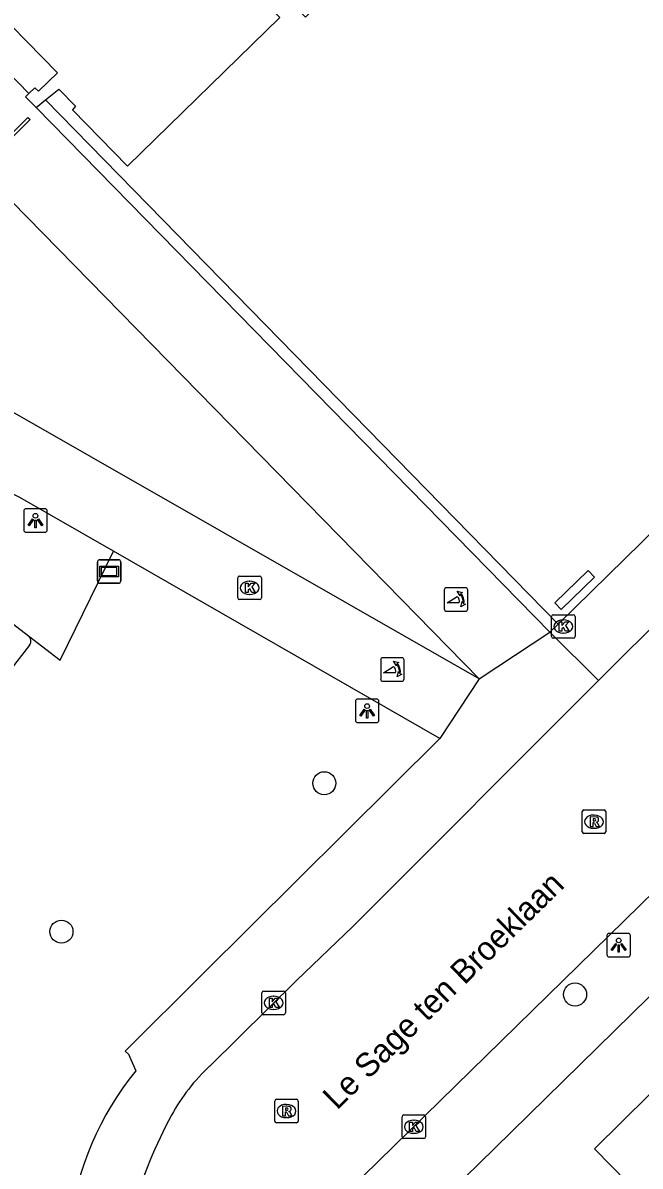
# Model space of a CAD drawing. Extents: x 161402 to 161933, y 381650 to 382313.
# Drawn here: x 161761.63 to 161787.85, y 382103.64 to 382152.18 of the extents above; entities that cross this region are included whole.
import ezdxf

# ---------------------------------------------------------------- set-up
doc = ezdxf.new("R2010")
doc.units = 0
for name, color, linetype in [('IMGEO_Boom', 7, 'Continuous'), ('IMGEO_Groenvoorziening', 7, 'Continuous'), ('IMGEO_Haag', 7, 'Continuous'), ('IMGEO_Kolk', 7, 'Continuous'), ('IMGEO_Lichtpunt', 7, 'Continuous'), ('IMGEO_Lijnafwatering', 7, 'Continuous'), ('IMGEO_Muur', 7, 'Continuous'), ('IMGEO_Openbare_ruimte_label', 7, 'Continuous'), ('IMGEO_Pand', 7, 'Continuous'), ('IMGEO_Pand_overbouw', 7, 'Continuous'), ('IMGEO_Parkeervlak_open', 7, 'Continuous'), ('IMGEO_Poller', 7, 'Continuous'), ('IMGEO_Reclamebord', 7, 'Continuous'), ('IMGEO_Rijbaan_lokaal_gesloten', 7, 'Continuous'), ('IMGEO_Rioolput', 7, 'Continuous'), ('IMGEO_Voetpad_open', 7, 'Continuous')]:
    doc.layers.add(name, color=color, linetype=linetype)

msp = doc.modelspace()

# ---------------------------------------------------------------- linework, layer by layer
at = {"layer": 'IMGEO_Boom'}
for centre in [(161774.437, 382119.897), (161763.272, 382113.595), (161785.089, 382110.925)]:
    msp.add_circle(centre, 0.489, dxfattribs=at)
at = {"layer": 'IMGEO_Groenvoorziening'}
msp.add_lwpolyline([(161761.867, 382126.157), (161763.216, 382125.122), (161765.481, 382129.756)], dxfattribs=at)
at = {"layer": 'IMGEO_Haag'}
msp.add_lwpolyline([(161784.501, 382127.274), (161784.224, 382127.562), (161785.644, 382128.928), (161785.921, 382128.64), (161784.501, 382127.274)], dxfattribs=at)
at = {"layer": 'IMGEO_Kolk'}
for p, q in [((161770.762, 382127.768), (161770.762, 382128.62)), ((161770.837, 382128.694), (161771.689, 382128.694)), ((161771.25, 382128.474), (161771.275, 382128.474)), ((161771.763, 382128.62), (161771.763, 382127.768)), ((161771.273, 382127.914), (161771.248, 382127.914)), ((161771.689, 382127.694), (161770.837, 382127.694)), ((161784.088, 382126.124), (161784.088, 382126.976)), ((161784.163, 382127.05), (161785.015, 382127.05)), ((161785.089, 382126.976), (161785.089, 382126.124)), ((161784.576, 382126.83), (161784.601, 382126.83)), ((161785.015, 382126.05), (161784.163, 382126.05)), ((161784.599, 382126.27), (161784.574, 382126.27)), ((161771.782, 382110.142), (161771.782, 382110.994)), ((161771.857, 382111.068), (161772.709, 382111.068)), ((161772.27, 382110.848), (161772.295, 382110.848)), ((161772.783, 382110.994), (161772.783, 382110.142)), ((161772.709, 382110.068), (161771.857, 382110.068)), ((161772.293, 382110.288), (161772.268, 382110.288)), ((161777.739, 382104.884), (161777.739, 382105.736)), ((161777.814, 382105.81), (161778.666, 382105.81)), ((161778.227, 382105.59), (161778.252, 382105.59)), ((161778.74, 382105.736), (161778.74, 382104.884)), ((161778.25, 382105.03), (161778.225, 382105.03)), ((161778.666, 382104.81), (161777.814, 382104.81))]:
    msp.add_line(p, q, dxfattribs=at)
for points in [[(161770.762, 382127.768), (161770.762, 382128.62)], [(161770.837, 382128.694), (161771.689, 382128.694)], [(161771.083, 382128.394), (161771.206, 382128.394), (161771.206, 382128.243), (161771.336, 382128.394), (161771.5, 382128.394), (161771.354, 382128.243), (161771.507, 382127.994), (161771.355, 382127.994), (161771.27, 382128.158), (161771.206, 382128.091), (161771.206, 382127.994), (161771.083, 382127.994), (161771.083, 382128.394)], [(161771.763, 382128.62), (161771.763, 382127.768)], [(161771.689, 382127.694), (161770.837, 382127.694)], [(161784.088, 382126.124), (161784.088, 382126.976)], [(161784.163, 382127.05), (161785.015, 382127.05)], [(161785.089, 382126.976), (161785.089, 382126.124)], [(161784.409, 382126.75), (161784.532, 382126.75), (161784.532, 382126.599), (161784.662, 382126.75), (161784.826, 382126.75), (161784.68, 382126.599), (161784.833, 382126.35), (161784.681, 382126.35), (161784.596, 382126.514), (161784.532, 382126.447), (161784.532, 382126.35), (161784.409, 382126.35), (161784.409, 382126.75)], [(161785.015, 382126.05), (161784.163, 382126.05)], [(161771.782, 382110.142), (161771.782, 382110.994)], [(161771.857, 382111.068), (161772.709, 382111.068)], [(161772.783, 382110.994), (161772.783, 382110.142)], [(161772.103, 382110.768), (161772.226, 382110.768), (161772.226, 382110.617), (161772.356, 382110.768), (161772.52, 382110.768), (161772.374, 382110.617), (161772.527, 382110.368), (161772.375, 382110.368), (161772.29, 382110.532), (161772.226, 382110.465), (161772.226, 382110.368), (161772.103, 382110.368), (161772.103, 382110.768)], [(161772.709, 382110.068), (161771.857, 382110.068)], [(161777.739, 382104.884), (161777.739, 382105.736)], [(161777.814, 382105.81), (161778.666, 382105.81)], [(161778.06, 382105.51), (161778.183, 382105.51), (161778.183, 382105.359), (161778.313, 382105.51), (161778.477, 382105.51), (161778.331, 382105.359), (161778.484, 382105.11), (161778.332, 382105.11), (161778.247, 382105.274), (161778.183, 382105.207), (161778.183, 382105.11), (161778.06, 382105.11), (161778.06, 382105.51)], [(161778.74, 382105.736), (161778.74, 382104.884)], [(161778.666, 382104.81), (161777.814, 382104.81)]]:
    msp.add_lwpolyline(points, dxfattribs=at)
for centre, start, end in [((161770.839, 382128.618), 91.552, 178.448), ((161770.839, 382128.618), 91.552, 178.448), ((161771.687, 382128.618), 1.552, 88.448), ((161771.687, 382128.618), 1.552, 88.448), ((161770.839, 382127.77), 181.552, 268.448), ((161770.839, 382127.77), 181.552, 268.448), ((161771.687, 382127.77), 271.552, 358.448), ((161771.687, 382127.77), 271.552, 358.448), ((161784.165, 382126.974), 91.552, 178.448), ((161784.165, 382126.974), 91.552, 178.448), ((161785.013, 382126.974), 1.552, 88.448), ((161785.013, 382126.974), 1.552, 88.448), ((161784.165, 382126.126), 181.552, 268.448), ((161784.165, 382126.126), 181.552, 268.448), ((161785.013, 382126.126), 271.552, 358.448), ((161785.013, 382126.126), 271.552, 358.448), ((161771.859, 382110.992), 91.552, 178.448), ((161771.859, 382110.992), 91.552, 178.448), ((161772.707, 382110.992), 1.552, 88.448), ((161772.707, 382110.992), 1.552, 88.448), ((161771.859, 382110.144), 181.552, 268.448), ((161771.859, 382110.144), 181.552, 268.448), ((161772.707, 382110.144), 271.552, 358.448), ((161772.707, 382110.144), 271.552, 358.448), ((161777.816, 382105.734), 91.552, 178.448), ((161777.816, 382105.734), 91.552, 178.448), ((161778.664, 382105.734), 1.552, 88.448), ((161778.664, 382105.734), 1.552, 88.448), ((161777.816, 382104.886), 181.552, 268.448), ((161777.816, 382104.886), 181.552, 268.448), ((161778.664, 382104.886), 271.552, 358.448), ((161778.664, 382104.886), 271.552, 358.448)]:
    msp.add_arc(centre, 0.0765, start, end, dxfattribs=at)
for centre, major_axis, ratio, start_param, end_param in [((161771.249, 382128.194), (-0.387, 0.002), 0.722429, 4.712389, 7.853982), ((161771.274, 382128.194), (-0.39, 0.002), 0.717154, 1.570796, 4.712389), ((161784.575, 382126.55), (-0.387, 0.002), 0.722429, 4.712389, 7.853982), ((161784.6, 382126.55), (-0.39, 0.002), 0.717154, 1.570796, 4.712389), ((161772.269, 382110.568), (-0.387, 0.002), 0.722429, 4.712389, 7.853982), ((161772.294, 382110.568), (-0.39, 0.002), 0.717154, 1.570796, 4.712389), ((161778.226, 382105.31), (-0.387, 0.002), 0.722429, 4.712389, 7.853982), ((161778.251, 382105.31), (-0.39, 0.002), 0.717154, 1.570796, 4.712389)]:
    msp.add_ellipse(centre, major_axis=major_axis, ratio=ratio, start_param=start_param, end_param=end_param, dxfattribs=at)
at = {"layer": 'IMGEO_Lichtpunt'}
for p, q in [((161761.669, 382131.454), (161761.669, 382130.647)), ((161761.669, 382131.454), (161761.669, 382130.647)), ((161762.571, 382131.549), (161761.763, 382131.549)), ((161762.571, 382131.549), (161761.763, 382131.549)), ((161762.665, 382130.647), (161762.665, 382131.454)), ((161762.665, 382130.647), (161762.665, 382131.454)), ((161761.763, 382130.553), (161762.571, 382130.553)), ((161761.763, 382130.553), (161762.571, 382130.553)), ((161776.659, 382123.467), (161775.851, 382123.467)), ((161776.659, 382123.467), (161775.851, 382123.467)), ((161775.757, 382123.372), (161775.757, 382122.565)), ((161775.757, 382123.372), (161775.757, 382122.565)), ((161776.753, 382122.565), (161776.753, 382123.372)), ((161776.753, 382122.565), (161776.753, 382123.372)), ((161775.851, 382122.471), (161776.659, 382122.471)), ((161775.851, 382122.471), (161776.659, 382122.471)), ((161786.442, 382113.424), (161786.442, 382112.617)), ((161786.442, 382113.424), (161786.442, 382112.617)), ((161787.344, 382113.519), (161786.536, 382113.519)), ((161787.344, 382113.519), (161786.536, 382113.519)), ((161787.438, 382112.617), (161787.438, 382113.424)), ((161787.438, 382112.617), (161787.438, 382113.424)), ((161786.536, 382112.523), (161787.344, 382112.523)), ((161786.536, 382112.523), (161787.344, 382112.523))]:
    msp.add_line(p, q, dxfattribs=at)
for points in [[(161762.043, 382131.118), (161762.082, 382131.09), (161761.894, 382130.828), (161761.856, 382130.855), (161762.043, 382131.118)], [(161762.145, 382131.07), (161762.192, 382131.07), (161762.192, 382130.748), (161762.145, 382130.748), (161762.145, 382131.07)], [(161762.255, 382131.09), (161762.293, 382131.117), (161762.48, 382130.855), (161762.441, 382130.827), (161762.255, 382131.09)], [(161776.131, 382123.036), (161776.17, 382123.008), (161775.982, 382122.746), (161775.944, 382122.773), (161776.131, 382123.036)], [(161776.233, 382122.988), (161776.28, 382122.988), (161776.28, 382122.666), (161776.233, 382122.666), (161776.233, 382122.988)], [(161776.343, 382123.008), (161776.381, 382123.035), (161776.568, 382122.773), (161776.529, 382122.745), (161776.343, 382123.008)], [(161786.816, 382113.088), (161786.855, 382113.06), (161786.667, 382112.798), (161786.629, 382112.825), (161786.816, 382113.088)], [(161786.918, 382113.04), (161786.965, 382113.04), (161786.965, 382112.718), (161786.918, 382112.718), (161786.918, 382113.04)], [(161787.028, 382113.06), (161787.066, 382113.087), (161787.253, 382112.825), (161787.214, 382112.797), (161787.028, 382113.06)]]:
    msp.add_lwpolyline(points, dxfattribs=at)
for centre in [(161762.168, 382131.252), (161776.256, 382123.17), (161786.941, 382113.222)]:
    msp.add_circle(centre, 0.0994, dxfattribs=at)
for centre, start, end in [((161761.763, 382131.454), 90, 180), ((161761.763, 382131.454), 90, 180), ((161762.571, 382131.454), 0, 90), ((161762.571, 382131.454), 0, 90), ((161761.763, 382130.647), 180, 270), ((161761.763, 382130.647), 180, 270), ((161762.571, 382130.647), 270, 0), ((161762.571, 382130.647), 270, 360), ((161775.851, 382123.372), 90, 180), ((161775.851, 382123.372), 90, 180), ((161776.659, 382123.372), 0, 90), ((161776.659, 382123.372), 0, 90), ((161775.851, 382122.565), 180, 270), ((161775.851, 382122.565), 180, 270), ((161776.659, 382122.565), 270, 0), ((161776.659, 382122.565), 270, 360), ((161786.536, 382113.424), 90, 180), ((161786.536, 382113.424), 90, 180), ((161787.344, 382113.424), 0, 90), ((161787.344, 382113.424), 0, 90), ((161786.536, 382112.617), 180, 270), ((161786.536, 382112.617), 180, 270), ((161787.344, 382112.617), 270, 0), ((161787.344, 382112.617), 270, 360)]:
    msp.add_arc(centre, 0.0946, start, end, dxfattribs=at)
at = {"layer": 'IMGEO_Lijnafwatering'}
msp.add_lwpolyline([(161759.72, 382146.044), (161761.845, 382148.166), (161761.94, 382148.087), (161759.814, 382145.96)], dxfattribs=at)
at = {"layer": 'IMGEO_Muur'}
for points in [[(161762.597, 382148.916), (161784.374, 382126.65)], [(161784.015, 382126.305), (161762.198, 382148.594)], [(161784.374, 382126.65), (161784.015, 382126.305)], [(161769.279, 382111.799), (161765.984, 382108.524), (161766.123, 382108.385), (161766.425, 382107.684)]]:
    msp.add_lwpolyline(points, dxfattribs=at)
msp.add_arc((161776.479, 382099.495), 12.967, 140.8362, 172.8403, dxfattribs=at)
at = {"layer": 'IMGEO_Pand'}
for points in [[(161762.198, 382148.594), (161761.744, 382149.047), (161761.891, 382149.186), (161762.139, 382149.42), (161762.295, 382149.283), (161763.101, 382150.057), (161760.483, 382152.716), (161759.531, 382151.588), (161721.45, 382190.492)], [(161762.597, 382148.916), (161763.156, 382149.374), (161763.873, 382148.642), (161763.738, 382148.49), (161766.077, 382146.095), (161772.542, 382152.417), (161769.948, 382155.069), (161770.562, 382155.574), (161773.637, 382152.427), (161780.106, 382158.747), (161777.513, 382161.4), (161785.428, 382168.061), (161805.657, 382147.504)], [(161762.198, 382148.594), (161762.597, 382148.916)], [(161812.975, 382087.217), (161811.601, 382088.614), (161806.434, 382083.531), (161789.417, 382100.81), (161785.909, 382104.373), (161789.402, 382107.818), (161793.08, 382111.447), (161793.922, 382110.604), (161796.076, 382112.783), (161795.307, 382113.643), (161799.066, 382117.315), (161802.484, 382120.653), (161805.97, 382117.113), (161810.796, 382121.845), (161807.594, 382125.104), (161806.847, 382124.385), (161806.553, 382124.686), (161817.329, 382135.274)]]:
    msp.add_lwpolyline(points, dxfattribs=at)
at = {"layer": 'IMGEO_Pand_overbouw'}
msp.add_lwpolyline([(161761.891, 382149.186), (161762.139, 382149.42), (161762.295, 382149.283), (161763.101, 382150.057), (161760.483, 382152.716), (161759.531, 382151.588), (161721.45, 382190.492), (161731.074, 382199.9), (161733.12, 382201.899), (161732.627, 382202.397), (161718.426, 382188.506), (161732.696, 382173.838), (161734.999, 382171.47), (161749.249, 382156.824), (161751.751, 382159.273), (161759.445, 382151.424), (161759.582, 382151.549)], close=True, dxfattribs=at)
at = {"layer": 'IMGEO_Parkeervlak_open'}
for points in [[(161758.515, 382128.73), (161761.867, 382126.157)], [(161761.918, 382125.758), (161735.779, 382092.047)]]:
    msp.add_lwpolyline(points, dxfattribs=at)
msp.add_arc((161761.682, 382125.931), 0.292, 323.8139, 50.7541, dxfattribs=at)
at = {"layer": 'IMGEO_Poller'}
for p, q in [((161779.535, 382128.102), (161779.535, 382127.295)), ((161779.535, 382128.102), (161779.535, 382127.295)), ((161780.437, 382128.197), (161779.629, 382128.197)), ((161780.437, 382128.197), (161779.629, 382128.197)), ((161780.531, 382127.295), (161780.531, 382128.102)), ((161780.531, 382127.295), (161780.531, 382128.102)), ((161779.629, 382127.2), (161780.437, 382127.2)), ((161779.629, 382127.2), (161780.437, 382127.2)), ((161776.831, 382125.13), (161776.831, 382124.323)), ((161776.831, 382125.13), (161776.831, 382124.323)), ((161777.733, 382125.225), (161776.925, 382125.225)), ((161777.733, 382125.225), (161776.925, 382125.225)), ((161777.827, 382124.323), (161777.827, 382125.13)), ((161777.827, 382124.323), (161777.827, 382125.13)), ((161776.925, 382124.228), (161777.733, 382124.228)), ((161776.925, 382124.228), (161777.733, 382124.228))]:
    msp.add_line(p, q, dxfattribs=at)
for points in [[(161780.17, 382127.553), (161779.657, 382127.553), (161780.087, 382127.828)], [(161780.214, 382127.926), (161780.202, 382127.853), (161780.077, 382128.058)], [(161780.077, 382128.058), (161780.308, 382127.992), (161780.237, 382127.96)], [(161780.23, 382127.381), (161780.296, 382127.612), (161780.326, 382127.544)], [(161780.362, 382127.517), (161780.434, 382127.506), (161780.23, 382127.381)], [(161777.51, 382124.954), (161777.498, 382124.881), (161777.373, 382125.086)], [(161777.373, 382125.086), (161777.604, 382125.02), (161777.533, 382124.988)], [(161777.466, 382124.581), (161776.953, 382124.581), (161777.383, 382124.856)], [(161777.526, 382124.409), (161777.592, 382124.64), (161777.622, 382124.572)], [(161777.658, 382124.545), (161777.73, 382124.534), (161777.526, 382124.409)]]:
    msp.add_lwpolyline(points, dxfattribs=at)
for centre, radius, start, end in [((161779.629, 382128.102), 0.0946, 90, 180), ((161779.629, 382128.102), 0.0946, 90, 180), ((161779.842, 382127.603), 0.332, 351.3247, 42.4854), ((161779.856, 382127.613), 0.476, 351.7527, 41.1691), ((161779.856, 382127.613), 0.516, 349.3569, 42.2912), ((161780.437, 382128.102), 0.0946, 0, 90), ((161780.437, 382128.102), 0.0946, 0, 90), ((161779.629, 382127.295), 0.0946, 180, 270), ((161779.629, 382127.295), 0.0946, 180, 270), ((161780.437, 382127.295), 0.0946, 270, 0), ((161780.437, 382127.295), 0.0946, 270, 0), ((161776.925, 382125.13), 0.0946, 90, 180), ((161776.925, 382125.13), 0.0946, 90, 180), ((161777.152, 382124.641), 0.476, 351.7527, 41.1691), ((161777.152, 382124.641), 0.516, 349.3569, 42.2912), ((161777.733, 382125.13), 0.0946, 0, 90), ((161777.733, 382125.13), 0.0946, 0, 90), ((161777.138, 382124.631), 0.332, 351.3247, 42.4854), ((161776.925, 382124.323), 0.0946, 180, 270), ((161776.925, 382124.323), 0.0946, 180, 270), ((161777.733, 382124.323), 0.0946, 270, 0), ((161777.733, 382124.323), 0.0946, 270, 0)]:
    msp.add_arc(centre, radius, start, end, dxfattribs=at)
at = {"layer": 'IMGEO_Reclamebord'}
for p, q in [((161764.799, 382128.487), (161764.799, 382129.287)), ((161764.799, 382129.287), (161764.799, 382128.487)), ((161764.899, 382129.387), (161765.689, 382129.387)), ((161765.689, 382129.387), (161764.899, 382129.387)), ((161765.789, 382129.287), (161765.789, 382128.487)), ((161765.789, 382128.487), (161765.789, 382129.287)), ((161765.689, 382128.387), (161764.899, 382128.387)), ((161764.899, 382128.387), (161765.689, 382128.387))]:
    msp.add_line(p, q, dxfattribs=at)
for points in [[(161764.9, 382129.119), (161765.688, 382129.119), (161765.688, 382128.655), (161764.9, 382128.655), (161764.9, 382129.119)], [(161764.965, 382129.054), (161764.965, 382128.72), (161765.623, 382128.72), (161765.623, 382129.054), (161764.965, 382129.054)]]:
    msp.add_lwpolyline(points, dxfattribs=at)
for centre, start, end in [((161764.899, 382129.287), 90, 180), ((161764.899, 382129.287), 90, 180), ((161765.689, 382129.287), 0, 90), ((161765.689, 382129.287), 360, 90), ((161764.899, 382128.487), 180, 270), ((161764.899, 382128.487), 180, 270), ((161765.689, 382128.487), 270, 0), ((161765.689, 382128.487), 270, 0)]:
    msp.add_arc(centre, 0.1, start, end, dxfattribs=at)
at = {"layer": 'IMGEO_Rijbaan_lokaal_gesloten'}
for points in [[(161807.63, 382145.403), (161806.285, 382144.085), (161803.661, 382141.516), (161803.248, 382141.112), (161795.969, 382134.059), (161790.782, 382128.901), (161787.157, 382125.329), (161786.084, 382124.255)], [(161800.253, 382126.852), (161775.438, 382102.569)], [(161786.084, 382124.255), (161775.652, 382113.816), (161773.249, 382111.52), (161769.574, 382107.889)]]:
    msp.add_lwpolyline(points, dxfattribs=at)
for centre, radius, start, end in [((161775.26, 382101.771), 8.353, 132.9056, 151.1279), ((161787.37, 382095.431), 22.021, 151.8964, 174.2893)]:
    msp.add_arc(centre, radius, start, end, dxfattribs=at)
at = {"layer": 'IMGEO_Rioolput'}
for p, q in [((161785.392, 382117.837), (161785.392, 382118.689)), ((161785.467, 382118.763), (161786.319, 382118.763)), ((161786.393, 382118.689), (161786.393, 382117.837)), ((161785.88, 382118.543), (161785.905, 382118.543)), ((161786.319, 382117.763), (161785.467, 382117.763)), ((161785.903, 382117.983), (161785.878, 382117.983)), ((161772.405, 382106.477), (161773.257, 382106.477)), ((161772.33, 382105.551), (161772.33, 382106.403)), ((161772.818, 382106.257), (161772.843, 382106.257)), ((161773.331, 382106.403), (161773.331, 382105.551)), ((161772.841, 382105.697), (161772.816, 382105.697)), ((161773.257, 382105.477), (161772.405, 382105.477))]:
    msp.add_line(p, q, dxfattribs=at)
for points in [[(161785.392, 382117.837), (161785.392, 382118.689)], [(161785.467, 382118.763), (161786.319, 382118.763)], [(161786.393, 382118.689), (161786.393, 382117.837)], [(161785.981, 382118.461), (161785.729, 382118.463), (161785.729, 382118.063)], [(161785.729, 382118.063), (161785.853, 382118.063), (161785.853, 382118.225), (161785.864, 382118.225)], [(161785.907, 382118.382), (161785.853, 382118.382), (161785.853, 382118.301)], [(161785.853, 382118.301), (161785.905, 382118.301)], [(161785.911, 382118.196), (161785.982, 382118.063), (161786.122, 382118.063), (161786.057, 382118.189)], [(161786.319, 382117.763), (161785.467, 382117.763)], [(161772.405, 382106.477), (161773.257, 382106.477)], [(161772.33, 382105.551), (161772.33, 382106.403)], [(161772.919, 382106.175), (161772.667, 382106.177), (161772.667, 382105.777)], [(161772.845, 382106.096), (161772.791, 382106.096), (161772.791, 382106.015)], [(161772.791, 382106.015), (161772.843, 382106.015)], [(161773.331, 382106.403), (161773.331, 382105.551)], [(161772.667, 382105.777), (161772.791, 382105.777), (161772.791, 382105.939), (161772.802, 382105.939)], [(161772.849, 382105.91), (161772.92, 382105.777), (161773.06, 382105.777), (161772.995, 382105.903)], [(161773.257, 382105.477), (161772.405, 382105.477)]]:
    msp.add_lwpolyline(points, dxfattribs=at)
for centre, radius, start, end in [((161785.469, 382118.687), 0.0765, 91.552, 178.448), ((161785.469, 382118.687), 0.0765, 91.552, 178.448), ((161786.317, 382118.687), 0.0765, 1.552, 88.448), ((161786.317, 382118.687), 0.0765, 1.552, 88.448), ((161785.863, 382118.172), 0.0533, 26.0293, 88.6989), ((161785.889, 382118.49), 0.19, 274.7715, 282.9687), ((161785.913, 382118.286), 0.0964, 77.0061, 93.1865), ((161785.927, 382118.343), 0.0378, 276.6634, 79.6772), ((161785.98, 382118.351), 0.109, 350.3612, 89.416), ((161785.978, 382118.351), 0.112, 277.5842, 350.9817), ((161785.962, 382118.136), 0.108, 29.5134, 73.7905), ((161785.469, 382117.839), 0.0765, 181.552, 268.448), ((161785.469, 382117.839), 0.0765, 181.552, 268.448), ((161786.317, 382117.839), 0.0765, 271.552, 358.448), ((161786.317, 382117.839), 0.0765, 271.552, 358.448), ((161772.407, 382106.401), 0.0765, 91.552, 178.448), ((161772.407, 382106.401), 0.0765, 91.552, 178.448), ((161773.255, 382106.401), 0.0765, 1.552, 88.448), ((161773.255, 382106.401), 0.0765, 1.552, 88.448), ((161772.827, 382106.204), 0.19, 274.7715, 282.9687), ((161772.851, 382106), 0.0964, 77.0061, 93.1865), ((161772.865, 382106.057), 0.0378, 276.6634, 79.6772), ((161772.918, 382106.065), 0.109, 350.3612, 89.416), ((161772.916, 382106.065), 0.112, 277.5842, 350.9817), ((161772.407, 382105.553), 0.0765, 181.552, 268.448), ((161772.407, 382105.553), 0.0765, 181.552, 268.448), ((161772.801, 382105.886), 0.0533, 26.0293, 88.6989), ((161772.9, 382105.85), 0.108, 29.5134, 73.7905), ((161773.255, 382105.553), 0.0765, 271.552, 358.448), ((161773.255, 382105.553), 0.0765, 271.552, 358.448)]:
    msp.add_arc(centre, radius, start, end, dxfattribs=at)
for centre, major_axis, ratio, start_param, end_param in [((161785.879, 382118.263), (-0.387, 0.002), 0.722429, 4.712389, 7.853982), ((161785.904, 382118.263), (-0.39, 0.002), 0.717154, 1.570796, 4.712389), ((161772.817, 382105.977), (-0.387, 0.002), 0.722429, 4.712389, 7.853982), ((161772.842, 382105.977), (-0.39, 0.002), 0.717154, 1.570796, 4.712389)]:
    msp.add_ellipse(centre, major_axis=major_axis, ratio=ratio, start_param=start_param, end_param=end_param, dxfattribs=at)
at = {"layer": 'IMGEO_Voetpad_open'}
for points in [[(161784.374, 382126.65), (161805.657, 382147.504)], [(161759.272, 382146.53), (161759.72, 382146.044), (161759.814, 382145.96), (161781.022, 382124.329)], [(161781.022, 382124.329), (161753.587, 382140.004), (161753.075, 382140.488)], [(161765.481, 382129.756), (161761.508, 382132.036), (161760.865, 382132.357)], [(161779.35, 382121.795), (161765.481, 382129.756)], [(161762.821, 381997.456), (161773.703, 382076.916), (161776.756, 382099.569), (161777.238, 382100.058), (161781.67, 382104.382), (161804.249, 382126.529)], [(161781.022, 382124.329), (161784.015, 382126.305)], [(161786.084, 382124.255), (161784.015, 382126.305)], [(161781.022, 382124.329), (161779.35, 382121.795)], [(161779.35, 382121.795), (161769.279, 382111.799), (161765.984, 382108.524), (161766.123, 382108.385), (161766.425, 382107.684)]]:
    msp.add_lwpolyline(points, dxfattribs=at)
msp.add_arc((161776.479, 382099.495), 12.967, 140.8362, 172.8403, dxfattribs=at)

# ---------------------------------------------------------------- texts
at = {"layer": 'IMGEO_Openbare_ruimte_label'}
msp.add_text('Le Sage ten Broeklaan', height=1, rotation=44.4327, dxfattribs=at).set_placement((161774.976, 382105.992))

doc.saveas('drawing.dxf')
